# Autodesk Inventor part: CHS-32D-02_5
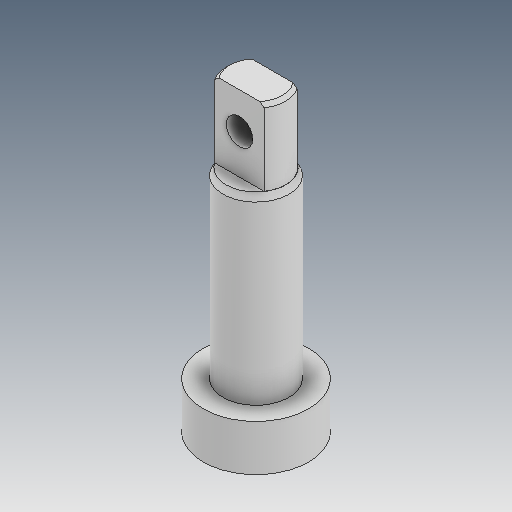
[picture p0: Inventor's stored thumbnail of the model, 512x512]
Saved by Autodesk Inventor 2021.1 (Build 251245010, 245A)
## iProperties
Created: 2021-05
Part Number: CHS-32D-02_5
Material: Ogólny
Document SubType Name: Modeling
Designer: user
Density: 1 g/cm^3
Appearance: Domyślna
Author: user
Revision Number: ÈÎºÎ
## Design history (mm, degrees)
feature "ÊäÈë1"
feature "ÊäÈë2"
node "Bryła1"
node "Bryła2"
